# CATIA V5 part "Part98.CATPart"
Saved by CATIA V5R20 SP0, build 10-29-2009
Part number: FA 063200-3
Revision: ANY
Definition: UNKNOWN
Nomenclature: FA 063200-3
Source: Unknown
Bounding box of the stored display mesh (mm): x -2.109 to 2.109, y -2.45 to 2.45, z -2 to 2
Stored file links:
  C:\Users\Utente\Desktop\IO LAVORO\3D X SITO CF\CUMSA\3D files FA\FA 063205-20\Part98.CATPart

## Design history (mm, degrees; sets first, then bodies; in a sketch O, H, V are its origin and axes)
Body1 "Chaflán4" (main body)
  Solid1: solid without history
